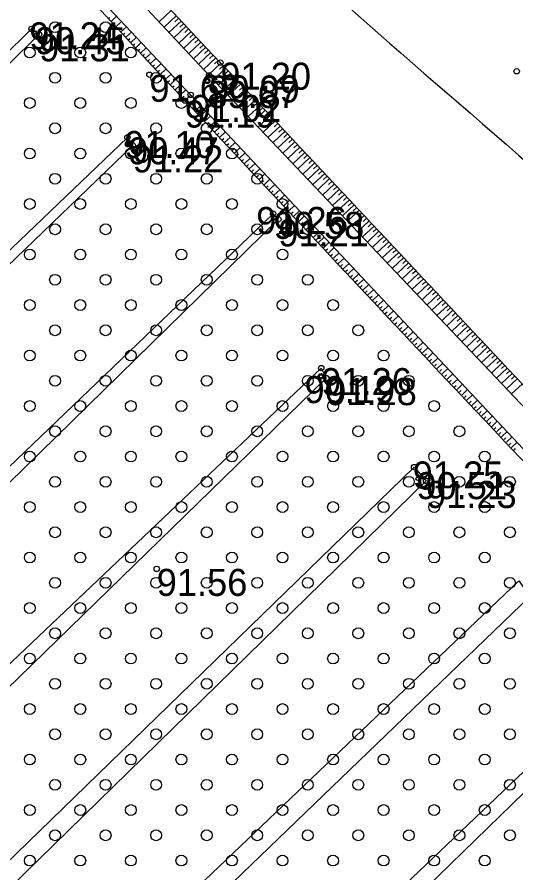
# Model space of a CAD drawing. Extents: x 316000 to 728450, y 314368 to 726000.
# Drawn here: x 725971.8 to 726040.8, y 315253.8 to 315372.4 of the extents above; entities that cross this region are included whole.
import ezdxf

# ---------------------------------------------------------------- set-up
doc = ezdxf.new("R2010")
doc.units = 0
for name, color, linetype in [('HIDG_ELEM_####_####_#', 7, 'Continuous'), ('HIDG_GRAV_####_####_#', 7, 'Continuous'), ('RELJ_AATZ_####_TKST_#', 7, 'Continuous'), ('RELJ_ELEM_####_####_#', 7, 'Continuous'), ('RELJ_HORZ_PAMT_####_#', 7, 'Continuous'), ('RELJ_NOGA_####_####_#', 7, 'Continuous'), ('TERT_ELEM_####_####_#', 7, 'Continuous')]:
    doc.layers.add(name, color=color, linetype=linetype)

msp = doc.modelspace()

# ---------------------------------------------------------------- linework, layer by layer
at = {"layer": 'HIDG_ELEM_####_####_#'}
for centre in [(725974.23, 315370.28), (725998.08, 315363.56), (725987.12, 315354.79), (726007.4, 315344.56), (726013.82, 315322.62), (726027.21, 315308.42)]:
    msp.add_circle(centre, 0.225, dxfattribs=at)
at = {"layer": 'HIDG_GRAV_####_####_#'}
for points in [[(726259.18, 315086.52), (726260.77, 315088.86), (726179.01, 315175.77), (726127.86, 315229.06), (726063.06, 315296.07), (725998.34, 315364.32), (725936.65, 315430.32), (725875.35, 315494.08), (725809.44, 315562.19), (725743.94, 315631.87)], [(725741.16, 315628.11), (725806.06, 315558.99), (725870.9, 315491.87), (725934.12, 315427.08), (725995.78, 315361.63), (726059.85, 315293.4), (726126.03, 315226.73), (726194.49, 315154.86), (726259.18, 315086.52)], [(725973.74, 315370.77), (725974.8, 315370.03), (725797.23, 315194.21), (725796.21, 315195.17), (725973.74, 315370.77)], [(725987.03, 315355.74), (725987.76, 315354.63), (725889.4, 315259.86), (725807.12, 315182.57), (725806.14, 315183.61), (725888.9, 315261.77), (725987.03, 315355.74)], [(726007.2, 315345.16), (726007.92, 315344.37), (725904.61, 315243.16), (725821.4, 315164.04), (725820.43, 315165.74), (725902.95, 315245.17), (726007.2, 315345.16)], [(726013.86, 315323.76), (726014.55, 315322.37), (725916.94, 315227.27), (725836.4, 315148.81), (725834.15, 315151.37), (725916.39, 315231.21), (726013.86, 315323.76)], [(726026.72, 315310.03), (726028.38, 315308.12), (725929.27, 315211.22), (725849.42, 315136.82), (725847.67, 315137.8), (725927.82, 315213.86), (726026.72, 315310.03)], [(726041.22, 315294.28), (726042.74, 315292.12), (725933.2, 315186.57), (725862.99, 315121.84), (725861.5, 315123.44), (725931.43, 315189.54), (726041.22, 315294.28)], [(726054.58, 315279.91), (726055.6, 315278.2), (725943.43, 315169.03), (725940.91, 315171.62), (726054.58, 315279.91)]]:
    msp.add_lwpolyline(points, dxfattribs=at)
at = {"layer": 'RELJ_ELEM_####_####_#'}
for centre in [(725973.74, 315370.77), (725974.8, 315370.03), (725999.9, 315366.09), (726040.93, 315364.9), (725990.07, 315364.42), (725998.08, 315363.56), (725998.34, 315364.32), (725995.78, 315361.63), (725994.98, 315360.84), (725987.03, 315355.74), (725987.12, 315354.79), (725987.76, 315354.63), (726007.2, 315345.16), (726007.92, 315344.37), (726013.86, 315323.76), (726013.82, 315322.62), (726014.55, 315322.37), (726026.72, 315310.03), (726028.38, 315308.12), (725991.08, 315295.93)]:
    msp.add_circle(centre, 0.375, dxfattribs=at)
at = {"layer": 'RELJ_HORZ_PAMT_####_#'}
for points in [[(726116.34, 315699.09), (726105.94, 315702.69), (726040.13, 315715), (725990.82, 315710.42), (725942.03, 315708.25), (725920.28, 315706.77), (725880.37, 315714.51), (725859.05, 315708.68), (725859.05, 315672.66), (725851.26, 315613.97), (725853.47, 315568.9), (725841, 315555.79), (725885.56, 315509.63), (725935.94, 315461.49), (725983.42, 315406.25), (726032.86, 315360.51), (726082.85, 315311.19), (726122.23, 315248.76), (726137.05, 315229.29), (726180.19, 315183.1), (726194.52, 315168.27), (726211.91, 315146.93), (726212.51, 315143.16)], [(726081.57, 315247.05), (726057.5, 315241.5), (726036.5, 315213.5), (725977, 315161), (725966.5, 315108.5), (725903.5, 315045.5), (725862.12, 315076.6), (725805.5, 315130), (725759.7, 315178.88), (725709.89, 315228.8), (725646.99, 315287.19), (725634.68, 315314.96), (725629.04, 315327.48), (725557.35, 315340.26), (725478.3, 315344.16)]]:
    msp.add_spline(points, degree=3, dxfattribs=at)
at = {"layer": 'RELJ_NOGA_####_####_#'}
for p, q in [((725993.08, 315373.31), (725991.41, 315371.73)), ((725984.36, 315372.12), (725984.61, 315372.35)), ((725984.71, 315371.76), (725985.52, 315372.52)), ((725993.77, 315372.58), (725992.09, 315371)), ((725994.11, 315372.22), (725993.61, 315371.74)), ((725985.05, 315371.39), (725985.29, 315371.62)), ((725985.39, 315371.03), (725986.2, 315371.79)), ((725985.73, 315370.66), (725985.98, 315370.89)), ((725986.08, 315370.3), (725986.89, 315371.06)), ((725994.45, 315371.85), (725992.78, 315370.27)), ((725995.14, 315371.13), (725993.46, 315369.54)), ((725994.8, 315371.49), (725994.29, 315371.01)), ((725986.42, 315369.93), (725986.66, 315370.16)), ((725986.76, 315369.57), (725987.57, 315370.34)), ((725995.83, 315370.4), (725994.14, 315368.81)), ((725996.51, 315369.67), (725994.82, 315368.08)), ((725995.48, 315370.76), (725994.98, 315370.29)), ((725996.17, 315370.04), (725995.66, 315369.56)), ((725987.1, 315369.21), (725987.35, 315369.44)), ((725987.45, 315368.84), (725988.26, 315369.61)), ((725987.79, 315368.48), (725988.03, 315368.71)), ((725988.13, 315368.11), (725988.95, 315368.88)), ((725997.2, 315368.95), (725995.51, 315367.35)), ((725996.86, 315369.31), (725996.35, 315368.83)), ((725997.54, 315368.58), (725997.04, 315368.1)), ((725988.47, 315367.75), (725988.72, 315367.98)), ((725988.81, 315367.38), (725989.63, 315368.15)), ((725989.5, 315366.66), (725990.32, 315367.42)), ((725997.89, 315368.22), (725996.19, 315366.61)), ((725998.57, 315367.49), (725996.87, 315365.88)), ((725998.23, 315367.86), (725997.72, 315367.37)), ((725989.16, 315367.02), (725989.4, 315367.25)), ((725989.84, 315366.29), (725990.09, 315366.52)), ((725990.18, 315365.93), (725991, 315366.7)), ((725999.26, 315366.76), (725997.56, 315365.15)), ((725998.92, 315367.13), (725998.41, 315366.65)), ((725999.6, 315366.4), (725999.09, 315365.92)), ((725990.53, 315365.56), (725990.77, 315365.79)), ((725990.87, 315365.2), (725991.69, 315365.97)), ((725991.21, 315364.84), (725991.46, 315365.07)), ((725991.56, 315364.47), (725992.37, 315365.24)), ((725999.95, 315366.04), (725998.24, 315364.42)), ((726000.63, 315365.31), (725998.93, 315363.7)), ((726000.29, 315365.67), (725999.78, 315365.19)), ((726000.98, 315364.95), (726000.47, 315364.46)), ((725991.9, 315364.11), (725992.14, 315364.34)), ((725992.24, 315363.74), (725993.06, 315364.51)), ((725992.93, 315363.01), (725993.75, 315363.79)), ((726001.32, 315364.58), (725999.61, 315362.97)), ((726002.01, 315363.86), (726000.3, 315362.25)), ((726001.66, 315364.22), (726001.15, 315363.74)), ((725992.58, 315363.38), (725992.83, 315363.61)), ((725993.27, 315362.65), (725993.51, 315362.88)), ((725993.61, 315362.29), (725994.43, 315363.06)), ((726002.69, 315363.13), (726000.99, 315361.52)), ((726002.35, 315363.49), (726001.84, 315363.01)), ((726003.04, 315362.76), (726002.53, 315362.28)), ((725993.95, 315361.92), (725994.2, 315362.15)), ((725994.3, 315361.56), (725995.12, 315362.33)), ((725994.64, 315361.19), (725994.89, 315361.43)), ((725994.98, 315360.83), (725995.8, 315361.6)), ((726003.38, 315362.4), (726001.68, 315360.8)), ((726004.07, 315361.67), (726002.36, 315360.07)), ((726003.72, 315362.04), (726003.21, 315361.56)), ((725995.33, 315360.47), (725995.57, 315360.7)), ((725995.67, 315360.1), (725996.49, 315360.87)), ((726004.75, 315360.95), (726003.05, 315359.35)), ((726005.44, 315360.22), (726003.74, 315358.62)), ((726004.41, 315361.31), (726003.9, 315360.83)), ((726005.09, 315360.58), (726004.58, 315360.1)), ((725996.01, 315359.74), (725996.26, 315359.97)), ((725996.35, 315359.37), (725997.17, 315360.14)), ((725996.7, 315359.01), (725996.94, 315359.24)), ((725997.04, 315358.65), (725997.86, 315359.42)), ((726006.12, 315359.49), (726004.43, 315357.9)), ((726005.78, 315359.85), (726005.27, 315359.37)), ((726006.46, 315359.13), (726005.96, 315358.65)), ((725997.38, 315358.28), (725997.63, 315358.51)), ((725997.72, 315357.92), (725998.54, 315358.69)), ((725998.41, 315357.19), (725999.23, 315357.96)), ((726006.81, 315358.76), (726005.12, 315357.17)), ((726007.49, 315358.03), (726005.8, 315356.44)), ((726007.15, 315358.4), (726006.64, 315357.92)), ((725998.07, 315357.55), (725998.31, 315357.78)), ((725998.75, 315356.83), (725999, 315357.06)), ((725999.1, 315356.46), (725999.91, 315357.23)), ((726008.18, 315357.3), (726006.49, 315355.72)), ((726007.84, 315357.67), (726007.33, 315357.19)), ((726008.52, 315356.94), (726008.01, 315356.46)), ((725999.44, 315356.1), (725999.68, 315356.33)), ((725999.78, 315355.73), (726000.59, 315356.5)), ((726000.12, 315355.37), (726000.37, 315355.6)), ((726000.47, 315355.01), (726001.28, 315355.77)), ((726008.86, 315356.58), (726007.18, 315354.99)), ((726009.55, 315355.85), (726007.87, 315354.27)), ((726009.21, 315356.21), (726008.7, 315355.74)), ((726009.89, 315355.48), (726009.39, 315355.01)), ((726000.81, 315354.64), (726001.05, 315354.87)), ((726001.15, 315354.28), (726001.96, 315355.04)), ((726001.84, 315353.55), (726002.65, 315354.31)), ((726010.23, 315355.12), (726008.56, 315353.54)), ((726010.92, 315354.39), (726009.24, 315352.82)), ((726010.57, 315354.75), (726010.07, 315354.28)), ((726001.5, 315353.91), (726001.74, 315354.14)), ((726002.18, 315353.19), (726002.42, 315353.41)), ((726002.52, 315352.82), (726003.33, 315353.58)), ((726011.6, 315353.66), (726009.93, 315352.09)), ((726011.26, 315354.03), (726010.76, 315353.55)), ((726011.94, 315353.3), (726011.44, 315352.83)), ((726002.87, 315352.46), (726003.11, 315352.69)), ((726003.21, 315352.09), (726004.02, 315352.85)), ((726003.55, 315351.73), (726003.79, 315351.96)), ((726003.89, 315351.37), (726004.7, 315352.13)), ((726012.29, 315352.93), (726010.62, 315351.37)), ((726012.97, 315352.2), (726011.31, 315350.64)), ((726012.63, 315352.57), (726012.13, 315352.1)), ((726004.24, 315351), (726004.48, 315351.23)), ((726004.58, 315350.64), (726005.39, 315351.4)), ((726013.66, 315351.47), (726011.99, 315349.92)), ((726014.34, 315350.74), (726012.68, 315349.19)), ((726013.31, 315351.84), (726012.81, 315351.37)), ((726014, 315351.11), (726013.5, 315350.64)), ((726004.92, 315350.27), (726005.16, 315350.5)), ((726005.27, 315349.91), (726006.07, 315350.67)), ((726005.61, 315349.55), (726005.85, 315349.77)), ((726005.95, 315349.18), (726006.75, 315349.94)), ((726015.02, 315350.02), (726013.37, 315348.46)), ((726014.68, 315350.38), (726014.19, 315349.91)), ((726015.37, 315349.65), (726014.87, 315349.19)), ((726006.29, 315348.82), (726006.53, 315349.04)), ((726006.64, 315348.45), (726007.44, 315349.21)), ((726006.98, 315348.09), (726007.22, 315348.32)), ((726007.32, 315347.72), (726008.12, 315348.48)), ((726015.71, 315349.29), (726014.06, 315347.74)), ((726016.39, 315348.56), (726014.75, 315347.01)), ((726016.05, 315348.92), (726015.56, 315348.46)), ((726007.66, 315347.36), (726007.9, 315347.59)), ((726008.01, 315347), (726008.81, 315347.75)), ((726017.08, 315347.83), (726015.44, 315346.29)), ((726016.73, 315348.19), (726016.24, 315347.73)), ((726017.42, 315347.46), (726016.93, 315347)), ((726008.35, 315346.63), (726008.59, 315346.86)), ((726008.69, 315346.27), (726009.49, 315347.02)), ((726009.03, 315345.9), (726009.27, 315346.13)), ((726009.38, 315345.54), (726010.18, 315346.29)), ((726017.76, 315347.1), (726016.12, 315345.56)), ((726018.44, 315346.37), (726016.81, 315344.84)), ((726018.1, 315346.73), (726017.61, 315346.27)), ((726018.79, 315346), (726018.3, 315345.54)), ((726009.72, 315345.18), (726009.96, 315345.4)), ((726010.06, 315344.81), (726010.86, 315345.56)), ((726010.75, 315344.08), (726011.55, 315344.84)), ((726019.13, 315345.64), (726017.5, 315344.11)), ((726019.81, 315344.91), (726018.19, 315343.39)), ((726019.47, 315345.27), (726018.98, 315344.82)), ((726010.41, 315344.45), (726010.65, 315344.67)), ((726011.09, 315343.72), (726011.33, 315343.95)), ((726011.43, 315343.36), (726012.23, 315344.11)), ((726020.49, 315344.18), (726018.87, 315342.66)), ((726020.15, 315344.54), (726019.67, 315344.09)), ((726020.84, 315343.81), (726020.35, 315343.36)), ((726011.78, 315342.99), (726012.02, 315343.22)), ((726012.12, 315342.63), (726012.92, 315343.38)), ((726012.46, 315342.26), (726012.7, 315342.49)), ((726012.8, 315341.9), (726013.6, 315342.65)), ((726021.18, 315343.45), (726019.56, 315341.94)), ((726021.86, 315342.72), (726020.25, 315341.21)), ((726021.52, 315343.08), (726021.04, 315342.63)), ((726013.15, 315341.54), (726013.39, 315341.76)), ((726013.49, 315341.17), (726014.28, 315341.92)), ((726014.17, 315340.44), (726014.97, 315341.19)), ((726022.55, 315341.99), (726020.94, 315340.48)), ((726023.23, 315341.26), (726021.63, 315339.76)), ((726022.2, 315342.35), (726021.72, 315341.9)), ((726022.89, 315341.62), (726022.41, 315341.17)), ((726013.83, 315340.81), (726014.07, 315341.03)), ((726014.52, 315340.08), (726014.76, 315340.3)), ((726014.86, 315339.71), (726015.65, 315340.46)), ((726023.91, 315340.53), (726022.31, 315339.03)), ((726023.57, 315340.89), (726023.09, 315340.44)), ((726024.25, 315340.16), (726023.78, 315339.72)), ((726015.2, 315339.35), (726015.44, 315339.57)), ((726015.55, 315338.99), (726016.34, 315339.73)), ((726015.89, 315338.62), (726016.13, 315338.85)), ((726016.23, 315338.26), (726017.02, 315339)), ((726024.6, 315339.8), (726023, 315338.31)), ((726025.28, 315339.07), (726023.69, 315337.58)), ((726024.94, 315339.43), (726024.46, 315338.99)), ((726016.57, 315337.89), (726016.81, 315338.12)), ((726016.92, 315337.53), (726017.71, 315338.27)), ((726025.96, 315338.34), (726024.38, 315336.86)), ((726025.62, 315338.7), (726025.15, 315338.26)), ((726026.3, 315337.97), (726025.83, 315337.53)), ((726017.26, 315337.17), (726017.5, 315337.39)), ((726017.6, 315336.8), (726018.39, 315337.55)), ((726017.94, 315336.44), (726018.18, 315336.66)), ((726018.29, 315336.07), (726019.08, 315336.82)), ((726026.65, 315337.61), (726025.07, 315336.13)), ((726027.33, 315336.88), (726025.76, 315335.41)), ((726026.99, 315337.24), (726026.51, 315336.8)), ((726027.67, 315336.51), (726027.2, 315336.07)), ((726018.63, 315335.71), (726018.87, 315335.93)), ((726018.97, 315335.34), (726019.76, 315336.09)), ((726019.66, 315334.62), (726020.45, 315335.36)), ((726028.01, 315336.15), (726026.44, 315334.68)), ((726028.7, 315335.42), (726027.13, 315333.95)), ((726028.35, 315335.78), (726027.88, 315335.34)), ((726019.31, 315334.98), (726019.55, 315335.2)), ((726020, 315334.25), (726020.24, 315334.47)), ((726020.34, 315333.89), (726021.13, 315334.63)), ((726029.38, 315334.69), (726027.82, 315333.23)), ((726029.04, 315335.05), (726028.57, 315334.61)), ((726029.72, 315334.32), (726029.25, 315333.89)), ((726020.68, 315333.52), (726020.92, 315333.75)), ((726021.03, 315333.16), (726021.81, 315333.9)), ((726021.37, 315332.8), (726021.61, 315333.02)), ((726021.71, 315332.43), (726022.5, 315333.17)), ((726030.06, 315333.96), (726028.51, 315332.5)), ((726030.75, 315333.23), (726029.2, 315331.78)), ((726030.4, 315333.59), (726029.94, 315333.16)), ((726022.06, 315332.07), (726022.29, 315332.29)), ((726022.4, 315331.7), (726023.18, 315332.44)), ((726023.08, 315330.97), (726023.87, 315331.71)), ((726031.43, 315332.5), (726029.88, 315331.05)), ((726032.11, 315331.77), (726030.57, 315330.33)), ((726031.09, 315332.86), (726030.62, 315332.43)), ((726031.77, 315332.13), (726031.31, 315331.7)), ((726022.74, 315331.34), (726022.98, 315331.56)), ((726023.43, 315330.61), (726023.66, 315330.83)), ((726023.77, 315330.25), (726024.55, 315330.98)), ((726032.8, 315331.04), (726031.26, 315329.6)), ((726032.45, 315331.4), (726031.99, 315330.97)), ((726033.14, 315330.67), (726032.68, 315330.24)), ((726024.11, 315329.88), (726024.35, 315330.1)), ((726024.45, 315329.52), (726025.24, 315330.26)), ((726024.8, 315329.15), (726025.03, 315329.38)), ((726025.14, 315328.79), (726025.92, 315329.53)), ((726033.48, 315330.31), (726031.95, 315328.87)), ((726034.16, 315329.58), (726032.64, 315328.15)), ((726033.82, 315329.94), (726033.36, 315329.51)), ((726025.48, 315328.43), (726025.72, 315328.65)), ((726025.82, 315328.06), (726026.61, 315328.8)), ((726034.85, 315328.85), (726033.32, 315327.42)), ((726034.5, 315329.21), (726034.05, 315328.78)), ((726035.19, 315328.48), (726034.73, 315328.06)), ((726026.17, 315327.7), (726026.4, 315327.92)), ((726026.51, 315327.33), (726027.29, 315328.07)), ((726026.85, 315326.97), (726027.09, 315327.19)), ((726027.19, 315326.61), (726027.97, 315327.34)), ((726035.53, 315328.12), (726034.01, 315326.7)), ((726036.21, 315327.39), (726034.7, 315325.97)), ((726035.87, 315327.75), (726035.42, 315327.33)), ((726036.55, 315327.02), (726036.1, 315326.6)), ((726027.54, 315326.24), (726027.77, 315326.46)), ((726027.88, 315325.88), (726028.66, 315326.61)), ((726028.57, 315325.15), (726029.34, 315325.88)), ((726036.9, 315326.66), (726035.39, 315325.25)), ((726037.58, 315325.93), (726036.08, 315324.52)), ((726037.24, 315326.29), (726036.79, 315325.87)), ((726028.22, 315325.51), (726028.46, 315325.73)), ((726028.91, 315324.78), (726029.14, 315325)), ((726029.25, 315324.42), (726030.03, 315325.15)), ((726038.26, 315325.2), (726036.77, 315323.8)), ((726037.92, 315325.56), (726037.47, 315325.14)), ((726038.6, 315324.83), (726038.16, 315324.41)), ((726029.59, 315324.06), (726029.83, 315324.28)), ((726029.94, 315323.69), (726030.71, 315324.42)), ((726030.28, 315323.33), (726030.51, 315323.55)), ((726030.62, 315322.96), (726031.4, 315323.69)), ((726038.94, 315324.47), (726037.45, 315323.07)), ((726039.63, 315323.74), (726038.14, 315322.34)), ((726039.29, 315324.1), (726038.84, 315323.68)), ((726030.96, 315322.6), (726031.2, 315322.82)), ((726031.31, 315322.24), (726032.08, 315322.96)), ((726031.99, 315321.51), (726032.77, 315322.24)), ((726040.31, 315323.01), (726038.83, 315321.62)), ((726039.97, 315323.37), (726039.52, 315322.95)), ((726041, 315322.28), (726039.52, 315320.89)), ((726040.65, 315322.64), (726040.21, 315322.23)), ((726031.65, 315321.87), (726031.88, 315322.09)), ((726032.33, 315321.14), (726032.57, 315321.36)), ((726032.68, 315320.78), (726033.45, 315321.51)), ((726041.68, 315321.55), (726040.21, 315320.17)), ((726033.02, 315320.41), (726033.25, 315320.63)), ((726033.36, 315320.05), (726034.14, 315320.78)), ((726033.71, 315319.69), (726033.94, 315319.9)), ((726034.05, 315319.32), (726034.82, 315320.05)), ((726034.39, 315318.96), (726034.62, 315319.18)), ((726034.73, 315318.59), (726035.5, 315319.32)), ((726035.08, 315318.23), (726035.31, 315318.45)), ((726035.42, 315317.87), (726036.19, 315318.59)), ((726035.76, 315317.5), (726035.99, 315317.72)), ((726036.1, 315317.14), (726036.87, 315317.86)), ((726036.45, 315316.77), (726036.68, 315316.99)), ((726036.79, 315316.41), (726037.56, 315317.13)), ((726037.47, 315315.68), (726038.24, 315316.4)), ((726037.13, 315316.05), (726037.36, 315316.26)), ((726037.82, 315315.32), (726038.05, 315315.53)), ((726038.16, 315314.95), (726038.93, 315315.67)), ((726038.5, 315314.59), (726038.73, 315314.81)), ((726038.84, 315314.22), (726039.61, 315314.95)), ((726039.19, 315313.86), (726039.42, 315314.08)), ((726039.53, 315313.5), (726040.3, 315314.22)), ((726039.87, 315313.13), (726040.1, 315313.35)), ((726040.22, 315312.77), (726040.98, 315313.49)), ((726040.56, 315312.4), (726040.79, 315312.62))]:
    msp.add_line(p, q, dxfattribs=at)
for points in [[(726259.12, 315084.51), (726262.72, 315089.26), (726261.56, 315090.84), (726260.2, 315092.42), (726257.29, 315095.53), (726218.91, 315136.38), (726180.31, 315176.84), (726128.67, 315229.97), (726063.7, 315298.11), (725999.9, 315366.09), (725937.21, 315432.09), (725876.35, 315495.23), (725810.58, 315563.08), (725744.7, 315632.91)], [(725740.86, 315626.98), (725805.54, 315558.12), (725870.39, 315491.15), (725932.8, 315426.8), (725994.98, 315360.84), (726059.66, 315292.12), (726075.75, 315275.46), (726092.08, 315259.04), (726108.47, 315242.67), (726124.69, 315226.14), (726193.27, 315154.03), (726250.06, 315092.6), (726256.32, 315085.83), (726258.82, 315084.29), (726259.12, 315084.51)]]:
    msp.add_spline(points, degree=3, dxfattribs=at)
at = {"layer": 'TERT_ELEM_####_####_#'}
for centre in [(725977, 315371), (725984, 315371), (725973.5, 315367.5), (725980.5, 315367.5), (725987.5, 315367.5), (725977, 315364), (725984, 315364), (725991, 315364), (725973.5, 315360.5), (725980.5, 315360.5), (725987.5, 315360.5), (725994.5, 315360.5), (725977, 315357), (725984, 315357), (725991, 315357), (725998, 315357), (725973.5, 315353.5), (725980.5, 315353.5), (725987.5, 315353.5), (725994.5, 315353.5), (726001.5, 315353.5), (725977, 315350), (725984, 315350), (725991, 315350), (725998, 315350), (726005, 315350), (725973.5, 315346.5), (725980.5, 315346.5), (725987.5, 315346.5), (725994.5, 315346.5), (726001.5, 315346.5), (726008.5, 315346.5), (725977, 315343), (725984, 315343), (725991, 315343), (725998, 315343), (726005, 315343), (726012, 315343), (725973.5, 315339.5), (725980.5, 315339.5), (725987.5, 315339.5), (725994.5, 315339.5), (726001.5, 315339.5), (726008.5, 315339.5), (725977, 315336), (725984, 315336), (725991, 315336), (725998, 315336), (726005, 315336), (726012, 315336), (725973.5, 315332.5), (725980.5, 315332.5), (725987.5, 315332.5), (725994.5, 315332.5), (726001.5, 315332.5), (726008.5, 315332.5), (726015.5, 315332.5), (725977, 315329), (725984, 315329), (725991, 315329), (725998, 315329), (726005, 315329), (726012, 315329), (726019, 315329), (725973.5, 315325.5), (725980.5, 315325.5), (725987.5, 315325.5), (725994.5, 315325.5), (726001.5, 315325.5), (726008.5, 315325.5), (726015.5, 315325.5), (726022.5, 315325.5), (725977, 315322), (725984, 315322), (725991, 315322), (725998, 315322), (726005, 315322), (726012, 315322), (726019, 315322), (726026, 315322), (725973.5, 315318.5), (725980.5, 315318.5), (725987.5, 315318.5), (725994.5, 315318.5), (726001.5, 315318.5), (726008.5, 315318.5), (726015.5, 315318.5), (726022.5, 315318.5), (726029.5, 315318.5), (725977, 315315), (725984, 315315), (725991, 315315), (725998, 315315), (726005, 315315), (726012, 315315), (726019, 315315), (726026, 315315), (726033, 315315), (725973.5, 315311.5), (725980.5, 315311.5), (725987.5, 315311.5), (725994.5, 315311.5), (726001.5, 315311.5), (726008.5, 315311.5), (726015.5, 315311.5), (726022.5, 315311.5), (726029.5, 315311.5), (726036.5, 315311.5), (725977, 315308), (725984, 315308), (725991, 315308), (725998, 315308), (726005, 315308), (726012, 315308), (726019, 315308), (726026, 315308), (726033, 315308), (726040, 315308), (725973.5, 315304.5), (725980.5, 315304.5), (725987.5, 315304.5), (725994.5, 315304.5), (726001.5, 315304.5), (726008.5, 315304.5), (726015.5, 315304.5), (726022.5, 315304.5), (726029.5, 315304.5), (726036.5, 315304.5), (725977, 315301), (725984, 315301), (725991, 315301), (725998, 315301), (726005, 315301), (726012, 315301), (726019, 315301), (726026, 315301), (726033, 315301), (726040, 315301), (725973.5, 315297.5), (725980.5, 315297.5), (725987.5, 315297.5), (725994.5, 315297.5), (726001.5, 315297.5), (726008.5, 315297.5), (726015.5, 315297.5), (726022.5, 315297.5), (726029.5, 315297.5), (726036.5, 315297.5), (725977, 315294), (725984, 315294), (725991, 315294), (725998, 315294), (726005, 315294), (726012, 315294), (726019, 315294), (726026, 315294), (726033, 315294), (726040, 315294), (725973.5, 315290.5), (725980.5, 315290.5), (725987.5, 315290.5), (725994.5, 315290.5), (726001.5, 315290.5), (726008.5, 315290.5), (726015.5, 315290.5), (726022.5, 315290.5), (726029.5, 315290.5), (726036.5, 315290.5), (725977, 315287), (725984, 315287), (725991, 315287), (725998, 315287), (726005, 315287), (726012, 315287), (726019, 315287), (726026, 315287), (726033, 315287), (726040, 315287), (725973.5, 315283.5), (725980.5, 315283.5), (725987.5, 315283.5), (725994.5, 315283.5), (726001.5, 315283.5), (726008.5, 315283.5), (726015.5, 315283.5), (726022.5, 315283.5), (726029.5, 315283.5), (726036.5, 315283.5), (725977, 315280), (725984, 315280), (725991, 315280), (725998, 315280), (726005, 315280), (726012, 315280), (726019, 315280), (726026, 315280), (726033, 315280), (726040, 315280), (725973.5, 315276.5), (725980.5, 315276.5), (725987.5, 315276.5), (725994.5, 315276.5), (726001.5, 315276.5), (726008.5, 315276.5), (726015.5, 315276.5), (726022.5, 315276.5), (726029.5, 315276.5), (726036.5, 315276.5), (725977, 315273), (725984, 315273), (725991, 315273), (725998, 315273), (726005, 315273), (726012, 315273), (726019, 315273), (726026, 315273), (726033, 315273), (726040, 315273), (725973.5, 315269.5), (725980.5, 315269.5), (725987.5, 315269.5), (725994.5, 315269.5), (726001.5, 315269.5), (726008.5, 315269.5), (726015.5, 315269.5), (726022.5, 315269.5), (726029.5, 315269.5), (726036.5, 315269.5), (725977, 315266), (725984, 315266), (725991, 315266), (725998, 315266), (726005, 315266), (726012, 315266), (726019, 315266), (726026, 315266), (726033, 315266), (726040, 315266), (725973.5, 315262.5), (725980.5, 315262.5), (725987.5, 315262.5), (725994.5, 315262.5), (726001.5, 315262.5), (726008.5, 315262.5), (726015.5, 315262.5), (726022.5, 315262.5), (726029.5, 315262.5), (726036.5, 315262.5), (725977, 315259), (725984, 315259), (725991, 315259), (725998, 315259), (726005, 315259), (726012, 315259), (726019, 315259), (726026, 315259), (726033, 315259), (726040, 315259), (725973.5, 315255.5), (725980.5, 315255.5), (725987.5, 315255.5), (725994.5, 315255.5), (726001.5, 315255.5), (726008.5, 315255.5), (726015.5, 315255.5), (726022.5, 315255.5), (726029.5, 315255.5), (726036.5, 315255.5)]:
    msp.add_circle(centre, 0.75, dxfattribs=at)

# ---------------------------------------------------------------- texts
at = {"layer": 'RELJ_AATZ_####_TKST_#'}
for s, p in [('91.24', (725973.43, 315367.93)), ('90.45', (725974.2, 315367.26)), ('91.31', (725974.8, 315366.28)), ('91.20', (725999.9, 315362.34)), ('91.62', (725990.07, 315360.67)), ('90.99', (725998.34, 315360.57)), ('89.67', (725998.08, 315359.81)), ('91.02', (725995.78, 315357.88)), ('91.19', (725994.98, 315357.09)), ('91.10', (725986.58, 315352.87)), ('90.47', (725987.12, 315352)), ('91.22', (725987.76, 315350.88)), ('91.26', (726004.85, 315342.34)), ('90.58', (726007.27, 315341.66)), ('91.21', (726007.92, 315340.62)), ('91.26', (726013.86, 315320.01)), ('90.19', (726011.55, 315318.9)), ('91.28', (726014.55, 315318.62)), ('91.25', (726026.53, 315307.07)), ('90.51', (726027.04, 315305.59)), ('91.23', (726028.38, 315304.37)), ('91.56', (725991.08, 315292.18))]:
    msp.add_text(s, height=3.75, dxfattribs=at).set_placement(p)

doc.saveas('drawing.dxf')
